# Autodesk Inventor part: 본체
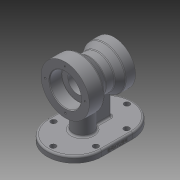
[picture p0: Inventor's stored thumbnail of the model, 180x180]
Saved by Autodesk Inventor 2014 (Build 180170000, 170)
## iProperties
Created: 2020-01
Part Number: 본체
Material: Generic
Document SubType Name: Modeling
Designer: kh
Density: 1 g/cm^3
Appearance: Default
Author: kh
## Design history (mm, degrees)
sketch "Sketch1"
  geometry: L1 (-25, -45)-(25, -45); L2 (25, 45)-(-25, 45); L3 (-25, -45)-(25, 45); L4 (25, -45)-(-25, 45); A1 r 45 centre (25, 0) between (25, -45) and (25, 45); A2 r 45 centre (-25, 0) between (-25, 45) and (-25, -45); 1 further point
  constraints: 8 end point, 4 point on circle, 2 centre point, 2 midpoint, 1 horizontal, 1 parallel
  dimensions: "d1" = 90 distance of L1.end L2.start; "d2" = 90 distance between parallel lines of L1 L2; "d3" = 45 radius of A2
extrude "Extrusion1" new body sketch "Sketch1" distance "d4" = 10; taper "d5" = 0 deg
sketch "Sketch3"
  geometry: L1 (0, 0)-(0, 80); L2 (-40, 80)-(40, 80); L3 (-25, 10)-(-70, 10) reference; L4 (-70, 10)-(-40, 10); L5 (-40, 80)-(-40, 120); L6 (-40, 120)-(-16, 120); L7 (-16, 120)-(-1.103, 107.5); L8 (-1.103, 107.5)-(13.289, 107.5); L9 (13.289, 107.5)-(24, 115); L10 (24, 115)-(40, 115); L11 (40, 115)-(40, 80)
  constraints: 20 end point, 4 perpendicular, 2 parallel, 1 point on line, 1 vertical
  dimensions: "d6" = 80 distance of L1.start L1.end; "d7" = 30 distance of L3.end L4.end; "d8" = 70 distance of L2.start L4.end; "d10" = 24 distance of L5.end L6.end; "d11" = 16 distance of L9.end L10.end; "d12" = 80 diameter of L6 L2; "d14" = 55 diameter of L8 L2; "d15" = 70 diameter of L10 L2; "d16" = 80 distance between parallel lines of L11 L5; "d17" = 40 deg angle of L8 L7; "d18" = 35 deg angle of L8 L9
revolve "Revolution1" sketch "Sketch3" stored, may be unused: angle "d19" = 90 deg
sketch "Sketch5"
  geometry: C1 r 40 at (0, 0) reference; C2 r 26 at (0, 0); 1 further point
  constraints: 1 centre point, 1 coincident
  dimensions: "d23" = 52 diameter of C2
extrude "Extrusion2" cut sketch "Sketch5" distance "d24" = 20; taper "d25" = 0 deg
sketch "Sketch6"
  geometry: C1 r 26 at (0, 0) reference; C2 r 16 at (0, 0); 1 further point
  constraints: 1 centre point, 1 coincident
  dimensions: "d26" = 32 diameter of C2
sketch "Sketch7"
  geometry: C1 r 35 at (0, 0) reference; C2 r 20 at (0, 0); 1 further point
  constraints: 1 centre point, 1 coincident
  dimensions: "d27" = 40 diameter of C2
extrude "Extrusion3" cut sketch "Sketch7" distance "d28" = 17; taper "d29" = 0 deg
extrude "Extrusion4" cut sketch "Sketch6" stored distance "d30" = 17; taper "d31" = 0 deg
sketch "Sketch8"
  geometry: L1 (25, 45)-(-25, 45) reference; L2 (70, 0)-(60, 0); L3 (-70, 0)-(-60, 0); L4 (25, -35)-(-25, -35); L5 (25, 35)-(-25, 35); A1 r 45 centre (25, 0) between (25, -45) and (25, 45) reference; A2 r 45 centre (-25, 0) between (-25, 45) and (-25, -45) reference; A3 r 35 centre (25, 0) between (25, -35) and (25, 35); A4 r 35 centre (-25, 0) between (-25, 35) and (-25, -35); 7 further points
  constraints: 8 coincident, 8 end point, 8 point on circle, 2 centre point, 2 tangent, 1 collinear, 1 parallel
  dimensions: "d32" = 10 distance of L2.start L2.end; "d33" = 10 distance of L3.start L3.end
hole "Hole1" sketch "Sketch8" at (25, -35), (60, 0), (25, 35), (-25, 35), (-60, 0), (-25, -35) diameter "d34" = 9; stored, may be unused: countersink angle "d38" = 90 deg, drill point angle "d40" = 118 deg; dims "d35" = 6, "d36" = 4, "d37" = 2, "d39" = 8
sketch "Sketch9"
  geometry: L1 (12, 0)-(12, -5); L2 (-3.199, -5)-(-25, -5); L3 (-25, 5)-(-3.199, 5); L4 (12, 5)-(12, 0); L5 (-25, -5)-(-30, -5); L6 (-30, -5)-(-30, 5); L7 (-30, 5)-(-25, 5); A1 r 45 centre (-25, 0) between (-25, 45) and (-25, -45) reference; A2 r 16 centre (12, 0) between (-3.199, -5) and (-3.199, 5); 1 further point
  constraints: 14 end point, 2 equal length, 2 perpendicular, 2 point on circle, 1 centre point
  dimensions: "d42" = 32 diameter of A2; "d43" = 37 distance of L1.start A1.centre (derived); "d44" = 5 distance of L1.start L1.end; "d45" = 37 distance of L1.end L2.end; "d46" = 10 distance of L2.end L3.start; "d70" = 5 distance of L2.end L5.end; "d71" = 10 distance of L5.end L6.end
sketch "Sketch11"
  geometry: C1 r 26 at (0, 0) reference; 2 further points
  dimensions: "d47" = 33 distance of C1.centre point (0, 33)
hole "Hole2" sketch "Sketch11" at (0, 33) diameter "d48" = 3.242; stored, may be unused: countersink angle "d52" = 90 deg, drill point angle "d54" = 118 deg; dims "d49" = 9, "d50" = 4, "d51" = 2, "d53" = 11
pattern_circular "Circular Pattern1" dims angle "d56" = 360 deg
sketch "Sketch13"
  geometry: 2 further points
extrude "Extrusion5" join sketch "Sketch9" stored distance "d72" = 17; taper "d73" = 0 deg
fillet "Fillet1" dims "d74" = 3
fillet "Fillet2" dims "d75" = 3
fillet "Fillet3" dims "d76" = 3
fillet "Fillet4" dims "d77" = 0.3
sketch "Sketch15"
  geometry: L1 (50, 0)-(0, 0) reference; L2 (95, 0)-(95, -7) reference; 2 further points
  constraints: 1 other
  dimensions: "d78" = 70 distance from line of point (25, -4) L2; "d79" = 4 distance from line of L1 point (25, -4)
emboss "Emboss1" sketch "Sketch15" dims "d1" = 90, "d2" = 90, "d3" = 45, "d80" = 0.5, "d81" = 0
sketch "Sketch17"
  geometry: C1 r 20 at (0, 0) reference; 2 further points
  dimensions: "d82" = 27.5 distance of C1.centre point (0, 27.5)
hole "Hole4" sketch "Sketch17" at (0, 27.5) diameter "d83" = 3.242; stored, may be unused: countersink angle "d87" = 90 deg, drill point angle "d89" = 118 deg; dims "d84" = 9, "d85" = 4, "d86" = 2, "d88" = 11
pattern_circular "Circular Pattern3" dims angle "d91" = 360 deg
chamfer "Chamfer1" distance "d93" = 1; stored, may be unused: second distance "d94" = 2, angle "d95" = 45 deg
body "Solid1"
